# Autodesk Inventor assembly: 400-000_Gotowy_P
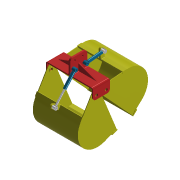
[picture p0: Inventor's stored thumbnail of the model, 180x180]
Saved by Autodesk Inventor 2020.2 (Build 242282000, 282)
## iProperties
Created: 2014-01
Part Number: 400-000_Gotowy_P
Document SubType Name: Assembly
Designer: F.Stasiak
Manager: www.cadconsulting.pl
Company: Fabian Stasiak CAD Consulting
Author: F.Stasiak
Subject: Zbiór ćwiczeń. Autodesk Inventor 2020. Kurs podstawowy
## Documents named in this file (4)
- C:\2020_Kurs_podstawowy\R6 Zespoły\Warsztat\Gotowe\400-000_Gotowy_P.iam
- C:\2020_Kurs_podstawowy\R6 Zespoły\Warsztat\Komponenty\400-001.ipt
- C:\2020_Kurs_podstawowy\R6 Zespoły\Warsztat\Komponenty\400-002.ipt
- C:\2020_Kurs_podstawowy\R6 Zespoły\Warsztat\Komponenty\S-100P.iam
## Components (5 placed, 3 different names)
1. 400-001:1 — Obrotowe:1, Obrotowe:2, Obrotowe:5, Obrotowe:7
2. 400-002:1 — Obrotowe:2, Obrotowe:6
3. 400-002:2 — Obrotowe:1, Obrotowe:8
4. S-100P:1 [sub-assembly] — Obrotowe:7, Obrotowe:8
5. S-100P:2 [sub-assembly] — Obrotowe:5, Obrotowe:6
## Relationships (6: RevoluteJoint 6)
- Obrotowe:1 [RevoluteJoint]: 400-001:1 ↔ 400-002:2
- Obrotowe:2 [RevoluteJoint]: 400-001:1 ↔ 400-002:1
- Obrotowe:5 [RevoluteJoint]: 400-001:1 ↔ S-100P:2
- Obrotowe:6 [RevoluteJoint]: 400-002:1 ↔ S-100P:2
- Obrotowe:7 [RevoluteJoint]: 400-001:1 ↔ S-100P:1
- Obrotowe:8 [RevoluteJoint]: 400-002:2 ↔ S-100P:1
